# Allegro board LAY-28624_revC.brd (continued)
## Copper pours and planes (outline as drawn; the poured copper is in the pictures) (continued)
EVDD on L6SIG: 37.21,67.82 37.21,45.72 37.46,45.47 39.37,45.47 39.62,45.72 39.62,66.8 54.1,81.28 54.1,104.52 57.21,107.63 59.37,107.63 61.09,109.35 61.09,119.63 52.83,127.89 52.07,127.89 51.82,127.64 51.82,126.11 59.05,118.87 59.05,109.98 58.55,109.47 56.01,109.47 52.07,105.54 52.07,82.68
MVREF_SLP on TOP: 225.68,145.03 226.06,145.41 226.31,145.41 226.44,145.29 226.44,144.53 226.06,144.14 222.88,144.14 222.76,144.27 222.76,144.91 222.88,145.03
OVDD_OSC_DDR on TOP: 84.96,109.98 84.84,110.11 81.92,110.11 79.5,107.7 79.5,106.93 79.76,106.68 84.71,106.68 84.96,106.93
OVDD_OSC_SYS on TOP: 78.87,100.33 78.87,98.81 79.25,98.43 83.19,98.43 83.44,98.68 83.44,100.71 83.31,100.84 81.28,100.84 81.03,100.58 79.12,100.58
USB1_VBUS on TOP: 105.66,19.05 105.66,17.4 106.42,16.64 106.42,13.97 104.77,12.32 104.77,11.68 105.15,11.3 106.04,11.3 107.18,12.45 107.18,19.05 107.06,19.18 105.79,19.18
USB2_VBUS on TOP: 103.75,19.18 105.02,19.18 105.15,19.05 105.15,17.53 106.17,16.51 106.17,14.35 105.91,14.1 105.02,14.1 104.77,14.35 104.77,16.13 103.63,17.27 103.63,19.05
VCORE on TOP: 132.59,104.01 132.33,104.27 132.33,115.06 132.46,115.19 134.62,115.19 135.13,114.68 135.13,104.14 135,104.01
VCORE on BOTTOM: 135.76,103.51 136.02,103.76 136.02,115.19 135.76,115.44 131.19,115.44 130.94,115.19 130.94,103.76 131.19,103.51
VCORE on L3SIG: 159.89,114.3 160.15,114.55 162.43,114.55 162.56,114.68 162.56,115.06 162.69,115.19 163.07,115.19 163.19,115.32 163.19,115.82 162.94,116.08 160.27,116.08 159.89,115.7 158.24,115.7 157.86,116.08 156.08,116.08 155.7,115.7 155.7,114.55 155.96,114.3
VCORE on L4PWR: 132.08,118.39 132.69,119 149.86,119 150.24,118.62 158.62,118.62 158.99,118.99 158.99,119.01 159.11,119.13 169.19,119.13 169.31,119 169.49,119 169.67,118.82 169.67,114.37 170.43,113.61 170.43,112.14 171.07,111.51 171.96,111.51 172.21,111.25 172.21,108.33 171.96,108.08 170.74,108.08 170.56,108.26 170.56,108.64 170.23,108.97 163.83,108.97 163.19,109.6 156.46,109.6 155.45,108.59 151.53,108.59 150.62,107.67 150.62,102.87 151.13,102.36 151.13,99.44 150.88,99.19 132.33,99.19 132.08,99.44
VCORE on L5PWR: 161.92,119 161.92,113.16 170.31,113.16 170.81,112.65 170.81,108.08 170.94,107.95 171.83,107.95 172.21,108.33 172.21,114.05 171.96,114.3 169.93,114.3 169.67,114.55 169.67,119
VCORE_SLP on TOP: 119.63,94.23 119.63,91.06 119.89,90.81 130.17,90.81 130.56,91.19 130.56,93.98 130.17,94.36 119.76,94.36
VCORE_SLP on BOTTOM: 128.02,108.46 129.03,109.47 130.3,109.47 130.43,109.6 130.43,115.06 130.05,115.44 123.95,115.44 123.7,115.19 123.7,110.36 122.3,108.97 122.3,93.09 124.46,90.93 130.17,90.93 130.56,91.31 130.56,97.16 128.02,99.7
VCORE_SLP on BOTTOM: 136.27,95.5 138.68,95.5 138.94,95.76 138.94,101.09 138.68,101.35 136.27,101.35 136.02,101.09 136.02,95.76
VCORE_SLP on L5PWR: 161.8,112.65 161.8,110.74 161.92,110.62 163.58,110.62 164.59,109.6 164.59,103.12 162.81,101.35 118.75,101.35 118.49,101.09 118.49,90.81 120.02,89.28 164.34,89.28 170.56,95.5 170.56,112.65 170.31,112.9 162.05,112.9
VTT on TOP: 148.34,164.97 149.86,164.97 150.37,165.48 150.37,165.73 150.62,165.99 151.51,165.99 151.64,165.86 151.64,164.08 151.26,163.7 148.46,163.7 148.21,163.96 148.21,164.85
VTT on TOP: 226.31,150.5 226.69,150.11 226.69,149.61 227.2,149.1 227.2,148.72 227.46,148.72 227.46,149.1 227.97,149.61 227.97,160.02 227.58,160.4 226.31,160.4 226.06,160.15 226.06,158.62 226.69,157.99 226.69,157.1 226.06,156.46 226.06,154.56 226.31,154.3
VTT on BOTTOM: 156.84,156.84 156.84,161.67 157.48,162.31 225.3,162.31 225.93,161.67 225.93,158.75 226.69,157.99 226.69,157.1 225.93,156.34 225.93,155.07 226.19,154.81 227.46,154.81 228.35,155.7 228.35,162.81 226.44,164.72 148.84,164.72 148.34,164.21 148.34,162.18 148.72,161.8 148.72,156.97 149.73,155.96 149.73,155.19 150.37,154.56 154.56,154.56
XVDD on BOTTOM: 193.93,129.92 193.93,127.38 196.09,127.38 196.34,127.64 196.34,129.67 196.09,129.92
XVDD on L4PWR: 172.47,108.46 172.47,111.78 172.72,112.04 172.72,119.63 172.97,119.89 177.65,119.89 187.94,130.17 195.96,130.17 196.22,129.92 196.22,123.17 188.24,115.19 185.55,115.19 184.66,114.3 184.66,111.63 181.23,108.2 172.72,108.2
XVDD on L5PWR: 174.37,119.76 172.97,119.76 172.72,119.51 172.72,108.97 172.97,108.71 174.37,108.71 174.62,108.97 174.62,119.51
N16879465 on TOP: 153.54,47.12 154.56,47.12 155.19,47.75 155.7,47.75 155.7,45.97 154.81,45.09 153.54,45.09 153.42,45.21 153.42,46.99
N16973728 on TOP: 131.32,47.75 132.33,47.75 132.97,48.39 133.48,48.39 133.48,46.61 132.59,45.72 131.32,45.72 131.19,45.85 131.19,47.62
N17021052 on TOP: 114.29,17.91 114.29,19.05 114.17,19.18 112.77,19.18 111.75,18.16 111.75,14.35 112.01,14.1 112.9,14.1 113.15,14.35 113.15,16.76
N17021059 on BOTTOM: 113.15,11.3 113.53,11.68 113.53,16.13 114.29,16.89 114.29,19.05 114.17,19.18 112.52,19.18 111.12,17.78 111.12,11.81 111.63,11.3
N17403382 on TOP: 59.94,134.75 61.34,134.75 61.72,134.37 63.63,134.37 64.9,135.64 66.8,135.64 67.18,135.25 67.18,134.49 66.68,133.98 65.53,133.98 63.25,131.7 63.25,129.03 62.61,128.4 61.21,128.4 60.58,129.03 60.58,132.72 59.69,133.6 59.69,134.49
N17403382 on BOTTOM: 64.64,135.76 64.64,127.64 65.28,127 65.28,125.6 65.79,125.09 67.69,125.09 68.58,125.98 68.58,135.64 67.95,136.27 65.15,136.27
N17403388 on TOP: 64.52,138.3 64.52,137.29 63.63,136.4 61.85,136.4 61.34,136.91 61.34,137.67 61.09,137.92 58.04,137.92 57.66,137.54 57.66,135.76 57.78,135.64 58.55,135.64 58.8,135.38 61.59,135.38 61.85,135.13 63.5,135.13 64.52,136.14 67.06,136.14 67.82,135.38 67.82,133.98 66.93,133.1 66.29,133.1 65.91,132.72 65.91,132.08 66.29,131.7 67.44,131.7 68.83,133.1 68.83,135.76 66.93,137.67 66.93,138.05 66.42,138.56 64.77,138.56
N17523733 on TOP: 57.4,135 58.42,135 58.67,134.75 58.67,129.16 58.42,128.91 57.66,128.91 57.28,129.29 57.28,133.1 56.52,133.86 54.36,133.86 54.1,134.11 54.1,135.25 54.36,135.51 56.9,135.51
N18263961 on TOP: 105.28,105.03 107.95,105.03 109.73,106.81 112.52,106.81 112.78,106.55 112.78,102.36 112.52,102.11 109.35,102.11 108.08,103.38 105.28,103.38 105.16,103.51 105.16,104.9
N18264005 on TOP: 119.25,109.09 127,109.09 127.38,108.71 127.38,95.12 127.25,95 120.4,95 119.63,95.76 119.63,98.55 118.87,99.31 118.87,108.71
N19644915 on TOP: 211.71,138.68 214,138.68 214.63,138.05 217.42,138.05 217.55,137.92 217.55,136.52 217.42,136.4 214.76,136.4 213.49,135.13 211.71,135.13 211.45,135.38 211.45,138.43
N19646811 on TOP (solid shape): 29.97,102.87 29.97,99.82 29.72,99.57 27.43,99.57 26.8,100.2 24,100.2 23.88,100.33 23.88,101.73 24,101.85 26.67,101.85 27.94,103.12 29.72,103.12
N19648273 on TOP (solid shape): 29.97,92.08 29.97,89.03 29.72,88.77 27.43,88.77 26.8,89.41 24,89.41 23.88,89.54 23.88,90.93 24,91.06 26.67,91.06 27.94,92.33 29.72,92.33
N19650144 on TOP (solid shape): 67.44,81.92 67.44,78.87 67.18,78.61 64.9,78.61 64.26,79.25 61.47,79.25 61.34,79.38 61.34,80.77 61.47,80.9 64.14,80.9 65.41,82.17 67.18,82.17
N19651609 on TOP (solid shape): 29.97,113.67 29.97,110.62 29.72,110.36 27.43,110.36 26.8,111 24,111 23.88,111.12 23.88,112.52 24,112.65 26.67,112.65 27.94,113.92 29.72,113.92
N19653096 on TOP (solid shape): 194.31,79.38 197.1,79.38 197.23,79.25 197.23,77.85 197.1,77.72 194.44,77.72 193.17,76.45 191.39,76.45 191.13,76.71 191.13,79.76 191.39,80.01 193.67,80.01
N23395649 on TOP (solid shape): 210.69,60.7 210.69,58.03 211.96,56.76 211.96,54.98 211.71,54.73 208.66,54.73 208.41,54.98 208.41,57.27 209.04,57.9 209.04,60.7 209.17,60.83 210.57,60.83
N23399971 on TOP (solid shape): 263.65,60.7 263.65,58.03 264.92,56.76 264.92,54.98 264.67,54.73 261.62,54.73 261.37,54.98 261.37,57.27 262,57.9 262,60.7 262.13,60.83 263.53,60.83
N24071716 on TOP: 257.56,82.04 257.94,81.66 257.94,75.44 257.68,75.18 255.91,75.18 255.65,75.44 255.65,81.79 255.91,82.04
N24071917 on TOP: 231.39,75.44 233.04,75.44 233.43,75.82 233.43,82.04 233.17,82.3 231.27,82.3 231.01,82.04 231.01,75.82

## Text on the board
Ref Des/Silkscreen Top: REMOTE | POWER | ON/OFF | CPLD_PROG | COP | RESET | 1.8V<->3.3V | SD_VDD_SEL | EVDD | PROG_SFP | FA_VDD | PROG_MTR | FULL_SPEED | ASLEEP | 0 | 1 | SYS_FAN1 | XGT1_FAN | SYS_FAN2 | SYS_FAN3 | XGT2_FAN | SYS_FAN4 | -> | SerDes_SEL | CPU_FAN | EMI2 | AQR105_JTAG | AQR105_SMB
PAGE_OUTLINE: FIGURE | SIZE | 10.0 | 16.0 | 19.69 | 27.56 | 35.43 | 39.37 | 43.31 | 45.28 | 51.18 | 55.12 | 62.99 | 90.55 | 133.86 | 59.06 | 61.02 | 92.52 | 96.06 | 96.46 | 125.98 | 127.95 | 146.06 | 157.48 | DRILL CHART: TOP to BOTTOM | ALL UNITS ARE IN MILS | PLATED | NON-PLATED | QTY | 3203 | 193 | 64 | 276 | 73 | 74 | 8 | 4 | 20 | 14 | 16 | 2 | 3
